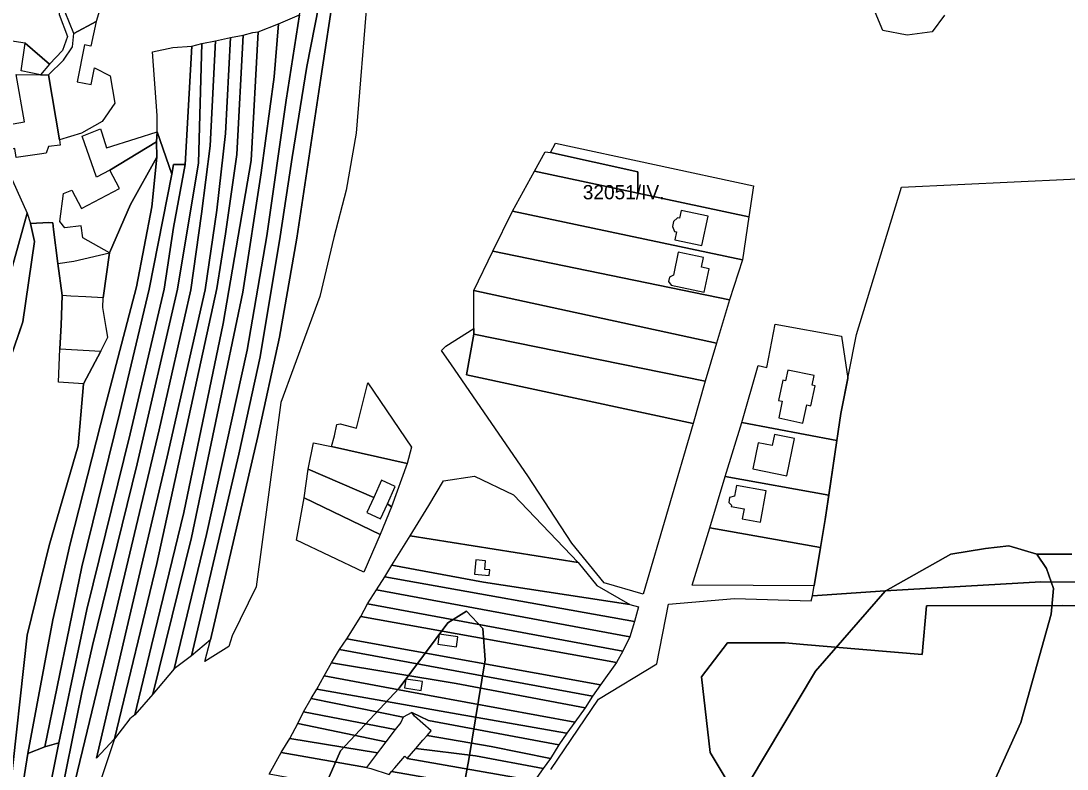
# Model space of a CAD drawing. Extents: x -532083 to -529270, y -1180561 to -1176456.
# Drawn here: x -531139.4 to -530772.6, y -1178758.4 to -1178495.9 of the extents above; entities that cross this region are included whole.
import ezdxf

# ---------------------------------------------------------------- set-up
doc = ezdxf.new("R2010")
doc.units = 0
for name, color, linetype in [('95560013', 7, 'Continuous'), ('95590013', 7, 'Continuous'), ('95600013', 7, 'Continuous'), ('95610013', 7, 'Continuous'), ('95620013', 7, 'Continuous'), ('95660013', 7, 'Continuous')]:
    doc.layers.add(name, color=color, linetype=linetype)

msp = doc.modelspace()

# ---------------------------------------------------------------- linework, layer by layer
at = {"layer": '95560013'}
for points in [[(-531074.8923, -1178720.61645), (-531072.8613, -1178713.04845), (-531056.3203, -1178641.73245), (-531048.7753, -1178606.80245), (-531042.6813, -1178572.16345), (-531034.2823, -1178516.02245), (-531029.4823, -1178484.28045), (-531022.9043, -1178482.14045), (-531017.9263, -1178487.66845), (-531021.8373, -1178535.28245), (-531025.3933, -1178555.25445), (-531029.6223, -1178571.87245), (-531034.5563, -1178592.53945), (-531048.1953, -1178629.79845), (-531056.9003, -1178694.41845), (-531065.3163, -1178711.59245), (-531066.4763, -1178715.37645)], [(-531126.0803, -1178749.18145), (-531116.3133, -1178702.36245), (-531101.1023, -1178640.77545), (-531089.2103, -1178590.00745), (-531085.8813, -1178568.37645), (-531081.7723, -1178546.24845), (-531079.5113, -1178504.73645), (-531075.8933, -1178503.82945), (-531077.1773, -1178545.67545), (-531084.5083, -1178590.00745), (-531098.6133, -1178651.31745), (-531114.2693, -1178715.03345), (-531117.9753, -1178731.52645), (-531125.0213, -1178766.13645), (-531131.6493, -1178806.63945), (-531134.3683, -1178838.24945), (-531139.0493, -1178839.01345), (-531135.9443, -1178809.10145), (-531129.4393, -1178766.13645)], [(-531114.2693, -1178715.03345), (-531098.6133, -1178651.31745), (-531084.5083, -1178590.00745), (-531077.1773, -1178545.67545), (-531075.8933, -1178503.82945), (-531071.1443, -1178502.92245), (-531073.0423, -1178539.78245), (-531076.0893, -1178563.57445), (-531079.8063, -1178590.28545), (-531090.8693, -1178639.38845), (-531108.7113, -1178714.10445), (-531121.2173, -1178765.89045), (-531126.0033, -1178791.98945), (-531128.7033, -1178817.47245), (-531130.1113, -1178837.90245), (-531134.3683, -1178838.24945), (-531131.6493, -1178806.63945), (-531125.0213, -1178766.13645), (-531117.9753, -1178731.52645)], [(-531086.5213, -1178549.65145), (-531091.6513, -1178534.78845), (-531091.6083, -1178529.04745), (-531093.2803, -1178506.82345), (-531086.0993, -1178505.29545), (-531079.5113, -1178504.73645), (-531081.7723, -1178546.24845), (-531085.8433, -1178546.24845)], [(-531128.2063, -1178705.96845), (-531122.1213, -1178679.33645), (-531109.9523, -1178631.62045), (-531098.8903, -1178589.17545), (-531093.4973, -1178561.17345), (-531091.7233, -1178543.75345), (-531091.8633, -1178538.37845), (-531091.6513, -1178534.78845), (-531086.5213, -1178549.65145), (-531094.4643, -1178590.00745), (-531104.6973, -1178633.28545), (-531117.9733, -1178687.38145), (-531130.9443, -1178750.57545), (-531136.9653, -1178752.89845)], [(-531130.9443, -1178750.57545), (-531117.9733, -1178687.38145), (-531104.6973, -1178633.28545), (-531094.4643, -1178590.00745), (-531086.5213, -1178549.65145), (-531085.8433, -1178546.24845), (-531081.7723, -1178546.24845), (-531085.8813, -1178568.37645), (-531089.2103, -1178590.00745), (-531101.1023, -1178640.77545), (-531116.3133, -1178702.36245), (-531126.0803, -1178749.18145)], [(-530781.7153, -1178692.62045), (-530836.3903, -1178695.78645), (-530861.8153, -1178697.61845), (-530857.3583, -1178670.82045), (-530851.9283, -1178633.59945), (-530846.3793, -1178605.97445), (-530830.6193, -1178554.28145), (-530771.3363, -1178551.46545), (-530741.6833, -1178549.05645), (-530685.6493, -1178546.03445), (-530682.6373, -1178595.14045), (-530687.7583, -1178603.90345), (-530688.8123, -1178610.55145), (-530691.4213, -1178624.48545), (-530705.1493, -1178654.45545), (-530706.7643, -1178660.12545), (-530707.1673, -1178675.11045), (-530706.3603, -1178682.60245), (-530705.2993, -1178690.54345), (-530742.1613, -1178692.82845)], [(-531019.2063, -1178689.24845), (-531042.7743, -1178678.05945), (-531040.0753, -1178663.26145), (-531013.4493, -1178676.07445)], [(-531148.5443, -1178829.55845), (-531143.9133, -1178796.33845), (-531136.9653, -1178752.89845), (-531130.9443, -1178750.57545), (-531126.0803, -1178749.18145), (-531129.4393, -1178766.13645), (-531135.9443, -1178809.10145), (-531139.0493, -1178839.01345), (-531150.2283, -1178843.15745)]]:
    msp.add_lwpolyline(points, close=True, dxfattribs=at)
at = {"layer": '95590013'}
for points in [[(-531137.8553, -1178503.70145), (-531143.3263, -1178502.88645), (-531143.3073, -1178501.82645), (-531143.8863, -1178490.19445), (-531130.6733, -1178490.75645), (-531130.4393, -1178485.26745), (-531134.5923, -1178485.14045), (-531134.5153, -1178481.24745), (-531125.7233, -1178483.28245), (-531125.9483, -1178493.68545), (-531123.0183, -1178501.37345), (-531124.8213, -1178506.34845), (-531129.3303, -1178511.09745)], [(-531112.9873, -1178496.17445), (-531120.8723, -1178500.28045), (-531123.8453, -1178492.89645), (-531123.6023, -1178480.25845), (-531114.4263, -1178481.56045), (-531108.4793, -1178480.88145)], [(-531053.1283, -1178571.29045), (-531046.3713, -1178523.69045), (-531041.7493, -1178493.73145), (-531041.3933, -1178491.94845), (-531039.2603, -1178484.63745), (-531038.3713, -1178482.14045), (-531033.5713, -1178483.21045), (-531039.0823, -1178511.92145), (-531044.2373, -1178543.84145), (-531048.4853, -1178571.58145), (-531055.4493, -1178613.78845), (-531062.9943, -1178647.84545), (-531079.5353, -1178718.57845), (-531085.6293, -1178723.23645), (-531074.3123, -1178676.08045), (-531060.0923, -1178611.46045)], [(-531048.4853, -1178571.58145), (-531044.2373, -1178543.84145), (-531039.0823, -1178511.92145), (-531033.5713, -1178483.21045), (-531029.4823, -1178484.28045), (-531034.2823, -1178516.02245), (-531042.6813, -1178572.16345), (-531048.7753, -1178606.80245), (-531056.3203, -1178641.73245), (-531072.8613, -1178713.04845), (-531079.5353, -1178718.57845), (-531062.9943, -1178647.84545), (-531055.4493, -1178613.78845)], [(-531125.8233, -1178537.65045), (-531129.7043, -1178514.80445), (-531124.5113, -1178509.71145), (-531121.3273, -1178504.99645), (-531120.8723, -1178500.28045), (-531112.9873, -1178496.17445), (-531114.8293, -1178504.80445), (-531117.1243, -1178504.34645), (-531119.6993, -1178517.26345), (-531114.7023, -1178518.25945), (-531113.5413, -1178512.43345), (-531108.1353, -1178515.18645), (-531106.4673, -1178524.76945), (-531110.8643, -1178531.15745), (-531118.1433, -1178535.26445)], [(-531068.4303, -1178602.05145), (-531058.7063, -1178544.88745), (-531056.2183, -1178499.74645), (-531049.1063, -1178497.00045), (-531050.6293, -1178515.55445), (-531055.1993, -1178549.16845), (-531061.5533, -1178591.11745), (-531079.5303, -1178677.11745), (-531093.0823, -1178732.04545), (-531099.4733, -1178739.37345), (-531093.6013, -1178714.96245), (-531082.2223, -1178668.37745)], [(-531061.5533, -1178591.11745), (-531055.1993, -1178549.16845), (-531050.6293, -1178515.55445), (-531049.1063, -1178497.00045), (-531041.7493, -1178493.73145), (-531046.3713, -1178523.69045), (-531053.1283, -1178571.29045), (-531060.0923, -1178611.46045), (-531074.3123, -1178676.08045), (-531085.6293, -1178723.23645), (-531093.0823, -1178732.04545), (-531079.5303, -1178677.11745)], [(-531112.8433, -1178754.52645), (-531102.7613, -1178710.96245), (-531088.1033, -1178648.82045), (-531074.8283, -1178590.28545), (-531070.6493, -1178562.26445), (-531067.6023, -1178535.41745), (-531065.9423, -1178501.78745), (-531061.4193, -1178500.88045), (-531063.6853, -1178542.83845), (-531067.6023, -1178570.55945), (-531070.6803, -1178589.73045), (-531091.6993, -1178686.27145), (-531106.5923, -1178747.73345)], [(-531067.6023, -1178570.55945), (-531063.6853, -1178542.83845), (-531061.4193, -1178500.88045), (-531058.0273, -1178499.97345), (-531056.2183, -1178499.74645), (-531058.7063, -1178544.88745), (-531068.4303, -1178602.05145), (-531082.2223, -1178668.37745), (-531093.6013, -1178714.96245), (-531099.4733, -1178739.37345), (-531101.2093, -1178740.76645), (-531106.5923, -1178747.73345), (-531091.6993, -1178686.27145), (-531070.6803, -1178589.73045)], [(-531132.5643, -1178514.80445), (-531139.3113, -1178513.47345), (-531137.8553, -1178503.70145), (-531129.3303, -1178511.09745)], [(-531079.8063, -1178590.28545), (-531076.0893, -1178563.57445), (-531073.0423, -1178539.78245), (-531071.1443, -1178502.92245), (-531065.9423, -1178501.78745), (-531067.6023, -1178535.41745), (-531070.6493, -1178562.26445), (-531074.8283, -1178590.28545), (-531088.1033, -1178648.82045), (-531102.7613, -1178710.96245), (-531112.8433, -1178754.52645), (-531106.5923, -1178747.73345), (-531114.2323, -1178770.89945), (-531115.2743, -1178775.95045), (-531120.3323, -1178835.01745), (-531126.3153, -1178836.74845), (-531130.1113, -1178837.90245), (-531128.7033, -1178817.47245), (-531126.0033, -1178791.98945), (-531121.2173, -1178765.89045), (-531108.7113, -1178714.10445), (-531090.8693, -1178639.38845)], [(-531141.0983, -1178543.87345), (-531141.5433, -1178540.67845), (-531143.8033, -1178541.24545), (-531147.1933, -1178532.46145), (-531156.9393, -1178519.71045), (-531154.8293, -1178517.16145), (-531148.2303, -1178515.93145), (-531145.3193, -1178532.55445), (-531138.1753, -1178531.30345), (-531141.0863, -1178514.67945), (-531132.5643, -1178514.80445), (-531129.7043, -1178514.80445), (-531125.8233, -1178537.65045), (-531125.6193, -1178539.49445), (-531129.7043, -1178540.00745), (-531130.5213, -1178542.26045), (-531132.8273, -1178542.64145)], [(-531091.8633, -1178538.37845), (-531108.2453, -1178548.26645), (-531112.9033, -1178550.73445), (-531117.9133, -1178536.38345), (-531111.4723, -1178533.81745), (-531111.0133, -1178535.18545), (-531109.3673, -1178540.39145), (-531098.9923, -1178537.11045), (-531091.6513, -1178534.78845)], [(-531108.3133, -1178577.24145), (-531117.7143, -1178571.96345), (-531118.2843, -1178567.74845), (-531124.0093, -1178568.52345), (-531125.7243, -1178566.32245), (-531124.4223, -1178556.45245), (-531121.5173, -1178555.29845), (-531118.1343, -1178561.68445), (-531104.8623, -1178554.65345), (-531108.2453, -1178548.26645), (-531091.8633, -1178538.37845), (-531091.7233, -1178543.75345), (-531100.9953, -1178560.31245)], [(-530884.1723, -1178564.63245), (-530923.0643, -1178556.30345), (-530923.0643, -1178548.85245), (-530953.6523, -1178542.05845), (-530951.8873, -1178538.77245), (-530882.4963, -1178553.72445)], [(-530923.0643, -1178556.30345), (-530959.3333, -1178548.63345), (-530955.6193, -1178541.83945), (-530953.6523, -1178542.05845), (-530923.0643, -1178548.85245)], [(-531209.5043, -1178823.95445), (-531192.7143, -1178748.24945), (-531184.9013, -1178716.23345), (-531175.0933, -1178681.04945), (-531158.9673, -1178620.35245), (-531144.4573, -1178547.23945), (-531137.1913, -1178563.30545), (-531158.8123, -1178641.15845), (-531176.1813, -1178704.26945), (-531184.8243, -1178746.78945), (-531199.6413, -1178817.14645)], [(-530886.3573, -1178579.75445), (-530966.9803, -1178562.65945), (-530959.3333, -1178548.63345), (-530923.0643, -1178556.30345), (-530884.1723, -1178564.63245)], [(-530890.9463, -1178593.78045), (-530973.9723, -1178576.68545), (-530966.9803, -1178562.65945), (-530886.3573, -1178579.75445)], [(-530900.6123, -1178574.68645), (-530898.4133, -1178564.41945), (-530907.8533, -1178562.41745), (-530908.4403, -1178565.15545), (-530909.2223, -1178564.98945), (-530910.5743, -1178566.28845), (-530910.9413, -1178568.00045), (-530910.2483, -1178569.78145), (-530909.4663, -1178569.94745), (-530910.0523, -1178572.68445)], [(-531199.6413, -1178817.14645), (-531184.8243, -1178746.78945), (-531176.1813, -1178704.26945), (-531158.8123, -1178641.15845), (-531137.1913, -1178563.30545), (-531136.0823, -1178567.01245), (-531134.6043, -1178573.31445), (-531138.6693, -1178601.49045), (-531146.0613, -1178622.99245), (-531150.3113, -1178640.60245), (-531160.7483, -1178677.84845), (-531169.5973, -1178702.41145), (-531179.6803, -1178746.78945), (-531185.4403, -1178780.39845), (-531192.4373, -1178811.77845)], [(-531116.6543, -1178592.72845), (-531121.9003, -1178592.50945), (-531124.9353, -1178592.24745), (-531126.3883, -1178580.95545), (-531120.8693, -1178580.20945), (-531108.3133, -1178577.24145), (-531110.5683, -1178593.08045)], [(-530895.5343, -1178608.90245), (-530980.5263, -1178590.49345), (-530973.9723, -1178576.68545), (-530890.9463, -1178593.78045)], [(-530899.8243, -1178591.05745), (-530898.0923, -1178582.88945), (-530900.7823, -1178582.31945), (-530900.0563, -1178578.89445), (-530908.9093, -1178577.01745), (-530910.6203, -1178585.08845), (-530911.9983, -1178585.79845), (-530912.3303, -1178587.36345), (-530911.3663, -1178588.61045)], [(-530899.4673, -1178622.27145), (-530980.5263, -1178605.83445), (-530980.5263, -1178590.49345), (-530895.5343, -1178608.90245)], [(-530853.3083, -1178643.06045), (-530886.5863, -1178636.77945), (-530880.9253, -1178616.83545), (-530877.8483, -1178617.45145), (-530874.8953, -1178602.30845), (-530851.6343, -1178606.49445), (-530849.4643, -1178621.33245), (-530851.9283, -1178633.59945)], [(-530903.6183, -1178637.17445), (-530983.1483, -1178620.07945), (-530980.5263, -1178605.83445), (-530899.4673, -1178622.27145)], [(-530862.4053, -1178630.93745), (-530860.9323, -1178623.88845), (-530861.9403, -1178623.67745), (-530861.2433, -1178620.34145), (-530870.4713, -1178618.41345), (-530871.2453, -1178622.11845), (-530872.2103, -1178621.91645), (-530873.7033, -1178629.06345), (-530872.4533, -1178629.32445), (-530873.6783, -1178635.18845), (-530865.1813, -1178636.96445), (-530863.8583, -1178630.63345)], [(-531003.9133, -1178651.16945), (-531030.5403, -1178645.21445), (-531029.4613, -1178641.42445), (-531028.5613, -1178637.45445), (-531027.4913, -1178637.26345), (-531021.7363, -1178638.72645), (-531017.7103, -1178622.88445), (-531002.4743, -1178645.39545)], [(-530856.1103, -1178662.26945), (-530892.4863, -1178655.70845), (-530886.5863, -1178636.77945), (-530853.3083, -1178643.06045)], [(-531015.6983, -1178663.10845), (-531038.6363, -1178653.15445), (-531036.8373, -1178643.95145), (-531030.5403, -1178645.21445), (-531003.9133, -1178651.16945), (-531009.4903, -1178666.32845), (-531010.8983, -1178665.28345), (-531008.1543, -1178659.22745), (-531012.9543, -1178657.05245)], [(-530868.0883, -1178642.44345), (-530875.1243, -1178640.98945), (-530875.9333, -1178644.89845), (-530880.8393, -1178643.88445), (-530882.7293, -1178653.02745), (-530870.7873, -1178655.49645)], [(-531013.4493, -1178676.07445), (-531040.0753, -1178663.26145), (-531038.6363, -1178653.15445), (-531015.6983, -1178663.10845), (-531018.0703, -1178668.34645), (-531013.2713, -1178670.52045), (-531010.8983, -1178665.28345), (-531009.4903, -1178666.32845)], [(-530943.9853, -1178685.84445), (-531002.8953, -1178676.56845), (-530996.3233, -1178665.91045), (-530991.2083, -1178657.22645), (-530980.3863, -1178655.64745), (-530966.6133, -1178662.16045)], [(-530858.9833, -1178680.59145), (-530897.7783, -1178673.68145), (-530892.4863, -1178655.70845), (-530856.1103, -1178662.26945), (-530857.3583, -1178670.82045)], [(-530885.8113, -1178667.11245), (-530886.4443, -1178670.58845), (-530880.1103, -1178671.74345), (-530878.1173, -1178660.81245), (-530888.4833, -1178658.92345), (-530889.1503, -1178662.58345), (-530890.9273, -1178663.13945), (-530891.2223, -1178664.89845), (-530890.2463, -1178665.75845), (-530890.2943, -1178666.29545)], [(-530925.8833, -1178700.64745), (-530977.2383, -1178692.75245), (-531009.3883, -1178686.83145), (-531002.8953, -1178676.56845), (-530943.9853, -1178685.84445), (-530937.4923, -1178693.93645)], [(-530858.9833, -1178680.59145), (-530861.2243, -1178694.06745), (-530904.0553, -1178693.87145), (-530897.7783, -1178673.68145)], [(-530924.2963, -1178706.58645), (-531011.7493, -1178690.97645), (-531009.3883, -1178686.83145), (-530977.2383, -1178692.75245), (-530925.8833, -1178700.64745), (-530922.8613, -1178701.46945)], [(-530975.0093, -1178688.47245), (-530976.7283, -1178688.31645), (-530976.4513, -1178685.26845), (-530979.8633, -1178684.95845), (-530980.3163, -1178689.95345), (-530975.1863, -1178690.41845)], [(-530925.8903, -1178712.02245), (-531014.7003, -1178695.51545), (-531011.7493, -1178690.97645), (-530924.2963, -1178706.58645)], [(-530928.2813, -1178716.97945), (-531017.8493, -1178700.44945), (-531014.7003, -1178695.51545), (-530925.8903, -1178712.02245)], [(-530930.5123, -1178720.97745), (-531020.2103, -1178704.79145), (-531017.8493, -1178700.44945), (-530928.2813, -1178716.97945)], [(-530936.1343, -1178728.80145), (-531025.1293, -1178712.68645), (-531020.2103, -1178704.79145), (-530930.5123, -1178720.97745)], [(-530938.9733, -1178732.78845), (-531027.6273, -1178716.44545), (-531025.1293, -1178712.68645), (-530936.1343, -1178728.80145)], [(-530992.6923, -1178711.03645), (-530993.1833, -1178714.49345), (-530986.6693, -1178715.41945), (-530986.1783, -1178711.96245)], [(-530986.8093, -1178728.37445), (-531030.4663, -1178721.06145), (-531027.6273, -1178716.44545), (-530938.9733, -1178732.78845), (-530941.5283, -1178736.91745)], [(-530945.2193, -1178741.90145), (-530996.1783, -1178732.50345), (-531033.1093, -1178725.67645), (-531030.4663, -1178721.06145), (-530986.8093, -1178728.37445), (-530941.5283, -1178736.91745)], [(-530945.2193, -1178741.90145), (-530947.9163, -1178745.74545), (-530948.0963, -1178745.71345), (-530986.0993, -1178739.05345), (-531035.6553, -1178730.29245), (-531033.1093, -1178725.67645), (-530996.1783, -1178732.50345)], [(-530998.6293, -1178727.69045), (-531004.3943, -1178726.82245), (-531004.8593, -1178729.90945), (-530999.0943, -1178730.77745)], [(-530996.4613, -1178741.33145), (-531002.2813, -1178738.48445), (-531005.4043, -1178740.19245), (-531037.6133, -1178733.63045), (-531035.6553, -1178730.29245), (-530986.0993, -1178739.05345), (-530948.0963, -1178745.71345), (-530947.9163, -1178745.74545), (-530950.7543, -1178749.87545)], [(-531008.2073, -1178744.42945), (-531040.2563, -1178738.24645), (-531037.6133, -1178733.63045), (-531005.4043, -1178740.19245), (-531006.2163, -1178741.96245)], [(-531011.4863, -1178748.77545), (-531042.3123, -1178742.37045), (-531040.2563, -1178738.24645), (-531008.2073, -1178744.42945)], [(-530974.4803, -1178750.42045), (-530997.0003, -1178746.60745), (-530995.5153, -1178744.88245), (-531001.4063, -1178739.80945), (-531002.2813, -1178738.48445), (-530996.4613, -1178741.33145), (-530950.7543, -1178749.87545), (-530953.7523, -1178754.64945)], [(-531014.4133, -1178752.65245), (-531045.0533, -1178747.67345), (-531042.3123, -1178742.37045), (-531011.4863, -1178748.77545), (-531013.3593, -1178751.24245)], [(-530979.9843, -1178753.70945), (-531000.9333, -1178751.17445), (-530998.4153, -1178748.25045), (-530997.0003, -1178746.60745), (-530974.4803, -1178750.42045), (-530953.7523, -1178754.64945), (-530956.2123, -1178758.17345)], [(-531018.1613, -1178757.82045), (-531048.1863, -1178752.58345), (-531045.0533, -1178747.67345), (-531014.4133, -1178752.65245)], [(-531002.5103, -1178769.36045), (-531052.3953, -1178760.14445), (-531048.1863, -1178752.58345), (-531018.1613, -1178757.82045), (-531016.6383, -1178758.17345), (-531010.3073, -1178760.21445), (-531009.4673, -1178759.23945), (-530962.5353, -1178767.33545), (-530967.6793, -1178775.28445)], [(-530962.5353, -1178767.33545), (-531009.4673, -1178759.23945), (-531008.2873, -1178757.86845), (-531004.8293, -1178753.85145), (-531003.9163, -1178754.63845), (-530959.2563, -1178762.51945)], [(-530959.2563, -1178762.51945), (-531003.9163, -1178754.63845), (-531000.9333, -1178751.17445), (-530979.9843, -1178753.70945), (-530956.2123, -1178758.17345)]]:
    msp.add_lwpolyline(points, close=True, dxfattribs=at)
for points in [[(-530815.5513, -1178493.96445), (-530819.8773, -1178499.71045), (-530828.6633, -1178500.90145), (-530837.2113, -1178499.23445), (-530839.8233, -1178492.80345)], [(-531143.3673, -1178767.76145), (-531137.2273, -1178711.43445), (-531129.5003, -1178679.88945), (-531119.2563, -1178644.91845), (-531117.4553, -1178623.21045), (-531111.4003, -1178611.77845), (-531108.9063, -1178606.89545), (-531109.5003, -1178603.44145), (-531110.6873, -1178596.41545), (-531110.5683, -1178593.08045), (-531108.3133, -1178577.24145), (-531100.9953, -1178560.31245), (-531091.7233, -1178543.75345), (-531093.4973, -1178561.17345), (-531098.8903, -1178589.17545), (-531109.9523, -1178631.62045), (-531122.1213, -1178679.33645), (-531128.2063, -1178705.96845), (-531136.9653, -1178752.89845), (-531143.9133, -1178796.33845)]]:
    msp.add_lwpolyline(points, dxfattribs=at)
at = {"layer": '95600013'}
msp.add_lwpolyline([(-530934.8273, -1178693.03745), (-530946.1623, -1178679.14145), (-530961.6343, -1178655.50145), (-530988.4413, -1178616.52045), (-530991.8883, -1178611.53245), (-530990.3583, -1178609.99845), (-530980.5263, -1178603.86245), (-530980.5263, -1178605.83445), (-530983.1483, -1178620.07945), (-530903.6183, -1178637.17445), (-530921.1543, -1178697.00745)], close=True, dxfattribs=at)
at = {"layer": '95610013'}
for points in [[(-530953.5453, -1178758.53945), (-530936.8713, -1178733.81145), (-530916.4713, -1178721.44245), (-530912.3603, -1178700.52045), (-530889.2193, -1178698.53545), (-530862.2713, -1178699.29845), (-530861.8153, -1178697.61845), (-530836.3903, -1178695.78645), (-530781.7153, -1178692.62045), (-530742.1613, -1178692.82845)], [(-530753.4283, -1178832.35745), (-530829.5283, -1178843.57645), (-530863.4053, -1178845.00045), (-530949.0293, -1178850.10345), (-530934.7623, -1178838.12245), (-530906.0623, -1178833.79545), (-530874.8743, -1178829.63545), (-530868.2383, -1178820.15045), (-530877.5263, -1178787.75445), (-530886.7353, -1178770.90145), (-530897.7213, -1178752.58845), (-530900.7903, -1178726.01145), (-530891.5813, -1178714.01945), (-530871.3873, -1178714.01945), (-530864.9643, -1178714.63945), (-530823.3393, -1178718.17045), (-530821.8903, -1178701.13745), (-530774.0523, -1178700.92945), (-530705.5063, -1178701.13745)], [(-530705.5063, -1178701.13745), (-530774.0523, -1178700.92945), (-530821.8903, -1178701.13745), (-530823.3393, -1178718.17045), (-530864.9643, -1178714.63945), (-530871.3873, -1178714.01945), (-530891.5813, -1178714.01945), (-530900.7903, -1178726.01145), (-530897.7213, -1178752.58845), (-530886.7353, -1178770.90145)]]:
    msp.add_lwpolyline(points, dxfattribs=at)
at = {"layer": '95620013'}
msp.add_lwpolyline([(-531146.0613, -1178622.99245), (-531138.6693, -1178601.49045), (-531134.6043, -1178573.31445), (-531136.0823, -1178567.01245), (-531129.5653, -1178566.64245), (-531128.1403, -1178566.76145), (-531127.9973, -1178569.06245), (-531126.3883, -1178580.95545), (-531124.9353, -1178592.24745), (-531125.2913, -1178602.60845), (-531125.7663, -1178610.94445), (-531111.4003, -1178611.77845), (-531117.4553, -1178623.21045), (-531119.2563, -1178644.91845), (-531129.5003, -1178679.88945), (-531137.2273, -1178711.43445), (-531143.3673, -1178767.76145)], dxfattribs=at)
at = {"layer": '95660013'}
for points in [[(-531143.3673, -1178767.76145), (-531137.2273, -1178711.43445), (-531129.5003, -1178679.88945), (-531119.2563, -1178644.91845), (-531117.4553, -1178623.21045), (-531126.2593, -1178622.60045), (-531125.7663, -1178610.94445), (-531125.2913, -1178602.60845), (-531124.9353, -1178592.24745), (-531126.3883, -1178580.95545), (-531127.9973, -1178569.06245), (-531128.1403, -1178566.76145), (-531129.5653, -1178566.64245), (-531136.0823, -1178567.01245), (-531134.6043, -1178573.31445), (-531138.6693, -1178601.49045), (-531140.1273, -1178605.73045)], [(-530770.8753, -1178683.00045), (-530783.1873, -1178683.00045), (-530793.0003, -1178680.00045), (-530801.1253, -1178681.00045), (-530813.3753, -1178683.00045), (-530836.3123, -1178696.00045), (-530860.8123, -1178724.00045), (-530884.0003, -1178763.00045)], [(-530884.0003, -1178763.00045), (-530860.8123, -1178724.00045), (-530836.3123, -1178696.00045), (-530813.3753, -1178683.00045), (-530801.1253, -1178681.00045), (-530793.0003, -1178680.00045), (-530783.1873, -1178683.00045), (-530779.8123, -1178688.00045), (-530777.3123, -1178695.00045), (-530778.1253, -1178704.00045), (-530788.8123, -1178742.00045), (-530806.0003, -1178780.00045)], [(-530806.0003, -1178780.00045), (-530788.8123, -1178742.00045), (-530778.1253, -1178704.00045), (-530777.3123, -1178695.00045), (-530779.8123, -1178688.00045), (-530783.1873, -1178683.00045), (-530770.8753, -1178683.00045)], [(-531131.1253, -1179033.00045), (-531104.0003, -1178956.00045), (-531085.8753, -1178900.00045), (-531071.6873, -1178863.00045), (-531061.1253, -1178836.00045), (-531045.6253, -1178794.00045), (-531027.3123, -1178752.00045), (-531006.8123, -1178730.00045), (-530989.6873, -1178707.00045), (-530983.1253, -1178703.00045), (-530977.3753, -1178709.00045), (-530976.6253, -1178720.00045), (-530982.3123, -1178755.00045), (-530986.3753, -1178777.00045), (-530983.8753, -1178805.00045), (-530977.4713, -1178831.83645), (-530979.6933, -1178839.26645), (-530987.3013, -1178865.17945), (-530992.1863, -1178881.81545), (-531005.5503, -1178926.69545), (-531009.6953, -1178948.12645), (-531029.3253, -1178985.34245)], [(-530986.3753, -1178777.00045), (-530982.3123, -1178755.00045), (-530976.6253, -1178720.00045), (-530977.3753, -1178709.00045), (-530983.1253, -1178703.00045), (-530989.6873, -1178707.00045), (-531006.8123, -1178730.00045), (-531027.3123, -1178752.00045), (-531045.6253, -1178794.00045)]]:
    msp.add_lwpolyline(points, dxfattribs=at)

# ---------------------------------------------------------------- texts
msp.add_text('32051/IV.', height=5, rotation=360, dxfattribs=at).set_placement((-530942.3711, -1178558.50045))

doc.saveas('drawing.dxf')
